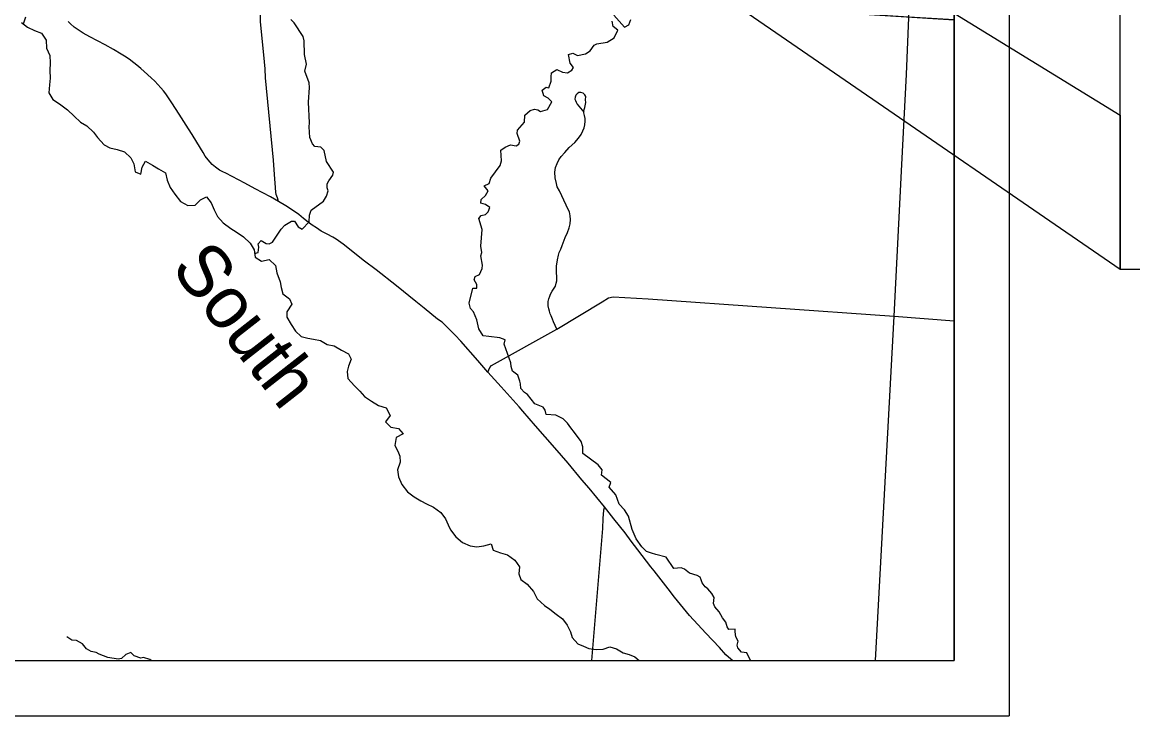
# Model space of a CAD drawing. Extents: x 0 to 91.3, y -0.7 to 22.
# Drawn here: x 7.212 to 9.224, y 14 to 15.256 of the extents above; entities that cross this region are included whole.
import ezdxf

# ---------------------------------------------------------------- set-up
doc = ezdxf.new("R2010")
doc.units = 0
for name, color, linetype in [('GM_X_City_Street', 7, 'Continuous'), ('GM_X_Corporation', 7, 'Continuous'), ('GM_X_County_Road', 7, 'Continuous'), ('GM_X_Major_River', 7, 'Continuous'), ('GM_X_Major_River_Text', 7, 'Continuous'), ('GM_X_Minor_River', 7, 'Continuous'), ('GM_X_Township_Road', 7, 'Continuous'), ('SH_Data', 7, 'Continuous'), ('SH_Text', 7, 'Continuous')]:
    doc.layers.add(name, color=color, linetype=linetype)

msp = doc.modelspace()

# ---------------------------------------------------------------- linework, layer by layer
at = {"layer": 'GM_X_City_Street'}
for points in [[(8.1801, 14.6999), (8.1746, 14.7132), (8.1727, 14.7177), (8.17, 14.7238), (8.1685, 14.7279), (8.1669, 14.7325), (8.1657, 14.7367), (8.1649, 14.742), (8.1645, 14.7461), (8.1649, 14.7499), (8.166, 14.7549), (8.1674, 14.7598), (8.1689, 14.7633), (8.1719, 14.7686), (8.1746, 14.7724), (8.1779, 14.7778), (8.179, 14.7831), (8.1801, 14.7873), (8.1801, 14.7922), (8.1801, 14.796), (8.18, 14.8013), (8.18, 14.8089), (8.1799, 14.8138), (8.1813, 14.8256), (8.1836, 14.8336), (8.1847, 14.8389), (8.1873, 14.8446), (8.1903, 14.8515), (8.1955, 14.8656), (8.1996, 14.8751), (8.2029, 14.8831), (8.2044, 14.8907), (8.2051, 14.8987), (8.2047, 14.9048), (8.2031, 14.9123), (8.2008, 14.9165), (8.1892, 14.9411), (8.1849, 14.9502), (8.181, 14.9577), (8.1795, 14.9638), (8.1771, 14.9736), (8.1767, 14.9839), (8.1777, 14.9923), (8.1811, 14.9995), (8.1837, 15.0067), (8.1882, 15.0125), (8.1946, 15.0197), (8.2025, 15.0285), (8.2131, 15.0377), (8.2199, 15.0454), (8.2244, 15.0522), (8.2274, 15.0591), (8.23, 15.0644), (8.2311, 15.0697), (8.2318, 15.0766), (8.2314, 15.0811), (8.2306, 15.0868), (8.2294, 15.0914), (8.229, 15.0955), (8.2308, 15.1009), (8.2326, 15.11), (8.2322, 15.1153), (8.2326, 15.121), (8.231, 15.124), (8.2283, 15.127), (8.2238, 15.1285), (8.2203, 15.1281), (8.2173, 15.1262), (8.2147, 15.1235), (8.2136, 15.1201), (8.2132, 15.1163), (8.214, 15.114), (8.2152, 15.1106), (8.2171, 15.1072), (8.2202, 15.1034), (8.229, 15.0925)], [(8.2668, 14.378), (8.2647, 14.3725), (8.2638, 14.3573), (8.2633, 14.3391), (8.2434, 14.1)]]:
    msp.add_lwpolyline(points, dxfattribs=at)
at = {"layer": 'GM_X_Corporation'}
msp.add_lwpolyline([(4.8242, 18.6326), (4.7833, 18.1361), (4.7799, 18.0944), (4.7688, 17.9561), (4.7562, 17.8002), (4.7391, 17.5254), (4.7381, 17.5094), (4.7369, 17.4842), (4.7039, 16.921), (4.6966, 16.7952), (4.624, 15.5538), (4.6241, 15.5494), (4.6027, 15.2253), (4.5901, 15.0403), (4.5616, 14.5843), (4.5361, 14.2234), (4.5273, 14.1), (8.9, 14.1), (8.9, 20.9)], dxfattribs=at)
for points in [[(4.5273, 14.1), (8.9, 14.1), (8.9, 15.2596), (8.8181, 15.2648), (7.6407, 15.3389), (7.1732, 15.3725), (6.438, 15.425), (5.7371, 15.476), (5.2553, 15.5081), (4.6241, 15.5494), (4.6027, 15.2253), (4.5901, 15.0403), (4.5616, 14.5843), (4.5361, 14.2234)], [(4.5286, 14.1), (8.9, 14.1), (8.9, 15.2593), (7.6407, 15.3389), (7.1732, 15.3725), (5.7332, 15.4763), (5.3098, 15.5058), (4.9415, 15.5315), (4.9055, 15.5345), (4.624, 15.5538)]]:
    msp.add_lwpolyline(points, close=True, dxfattribs=at)
at = {"layer": 'GM_X_County_Road'}
msp.add_lwpolyline([(8.4988, 14.1), (8.4959, 14.1024), (8.4868, 14.1105), (8.4748, 14.1237), (8.4501, 14.1497), (8.4359, 14.1653), (8.4209, 14.1816), (8.3934, 14.215), (8.3818, 14.2298), (8.357, 14.2621), (8.3507, 14.2697), (8.3273, 14.3005), (8.3152, 14.3159), (8.3039, 14.3309), (8.2837, 14.3564), (8.2668, 14.378), (8.253, 14.3954), (8.2391, 14.4119), (8.2259, 14.4271), (8.2006, 14.4576), (8.1769, 14.4853), (8.1419, 14.525), (8.1188, 14.5515), (8.1121, 14.5591), (8.0794, 14.5955), (8.0555, 14.6222), (8.0371, 14.6432), (8.0064, 14.678), (7.9963, 14.6889), (7.9873, 14.6981), (7.9802, 14.705), (7.9724, 14.7124), (7.9644, 14.7181), (7.9399, 14.7378), (7.9247, 14.7501), (7.8901, 14.7782), (7.8529, 14.8073), (7.8321, 14.8229), (7.7929, 14.8539), (7.7808, 14.8626), (7.7746, 14.8666), (7.7641, 14.8718), (7.7532, 14.8776), (7.7446, 14.8831), (7.7369, 14.8881), (7.7296, 14.8936), (7.7211, 14.9005), (7.7126, 14.9075), (7.7035, 14.9142), (7.6893, 14.9231), (7.6762, 14.931), (7.6617, 14.9393), (7.6339, 14.954), (7.6152, 14.9639), (7.5804, 14.9824), (7.5754, 14.985), (7.5693, 14.988), (7.5645, 14.9915), (7.5618, 14.9934), (7.5559, 14.998), (7.5521, 15.0021), (7.5486, 15.0067), (7.5433, 15.0132), (7.5395, 15.0196), (7.5345, 15.0273), (7.5194, 15.0521), (7.5128, 15.0624), (7.4961, 15.0894), (7.4828, 15.1099), (7.4756, 15.1204), (7.4718, 15.126), (7.4677, 15.1311), (7.4628, 15.1369), (7.452, 15.1488), (7.4455, 15.1549), (7.4326, 15.1665), (7.4265, 15.1719), (7.4194, 15.1781), (7.4141, 15.182), (7.4052, 15.1887), (7.3967, 15.1943), (7.3909, 15.1976), (7.377, 15.2063), (7.3618, 15.2147), (7.3478, 15.2217), (7.3344, 15.2289), (7.322, 15.236), (7.3058, 15.2469), (7.2993, 15.2524), (7.2948, 15.2566)], dxfattribs=at)
at = {"layer": 'GM_X_Major_River'}
for points in [[(7.2106, 15.2553), (7.2212, 15.2469), (7.2337, 15.2408), (7.2465, 15.2358), (7.2548, 15.2233), (7.2559, 15.2085), (7.2616, 15.1952), (7.2623, 15.1823), (7.2614, 15.1679), (7.2622, 15.1543), (7.261, 15.1421), (7.2598, 15.1277), (7.2669, 15.1159), (7.2794, 15.1079), (7.2934, 15.0969), (7.3059, 15.0855), (7.3172, 15.0744), (7.3285, 15.0679), (7.3406, 15.0565), (7.3482, 15.047), (7.3603, 15.0337), (7.3705, 15.0284), (7.3837, 15.0253), (7.397, 15.0207), (7.4083, 15.01), (7.414, 14.999), (7.4162, 14.985), (7.4268, 14.9807), (7.4291, 14.9929), (7.4348, 15.0042), (7.4477, 14.9966), (7.4587, 14.9901), (7.4715, 14.9832), (7.4741, 14.9699), (7.4798, 14.9563), (7.4881, 14.9441), (7.4982, 14.9308), (7.5115, 14.9239), (7.5248, 14.9246), (7.5347, 14.9341), (7.5453, 14.9393), (7.5543, 14.9283), (7.5592, 14.9162), (7.5656, 14.9036), (7.5758, 14.8922), (7.5894, 14.8819), (7.5993, 14.8758), (7.6125, 14.867), (7.6246, 14.8556), (7.6317, 14.8435), (7.634, 14.8302), (7.6453, 14.8229), (7.659, 14.8263), (7.6703, 14.8149), (7.6733, 14.802), (7.6793, 14.7857), (7.6811, 14.7754), (7.6837, 14.7637), (7.6962, 14.7549), (7.7004, 14.745), (7.6912, 14.7314), (7.6912, 14.7219), (7.6987, 14.7086), (7.7066, 14.6961), (7.7172, 14.6869), (7.7293, 14.6835), (7.7395, 14.6815), (7.752, 14.6792), (7.7645, 14.672), (7.777, 14.6697), (7.7899, 14.662), (7.8028, 14.6551), (7.8076, 14.6453), (7.8027, 14.6332), (7.8007, 14.6233), (7.8018, 14.6104), (7.8139, 14.5975), (7.8233, 14.5876), (7.832, 14.5777), (7.8445, 14.5697), (7.8574, 14.5617)], [(7.8574, 14.5617), (7.871, 14.5575), (7.8785, 14.5438), (7.8698, 14.5321), (7.8796, 14.5225), (7.8936, 14.5198), (7.9019, 14.5103), (7.889, 14.5035), (7.8867, 14.4892), (7.8923, 14.4793), (7.8957, 14.4698), (7.8964, 14.4592), (7.8914, 14.4455), (7.8933, 14.4323), (7.8997, 14.4186), (7.9099, 14.4053), (7.9216, 14.3961), (7.9337, 14.3889), (7.9443, 14.3839), (7.9571, 14.3774), (7.97, 14.3679), (7.9787, 14.3565), (7.9835, 14.3459), (7.9877, 14.3364), (7.9975, 14.3242), (8.0096, 14.3139), (8.0232, 14.3078), (8.0353, 14.3058), (8.0482, 14.3077), (8.0611, 14.3114), (8.0649, 14.3), (8.0781, 14.2951), (8.091, 14.2912), (8.1042, 14.2817), (8.1125, 14.2695), (8.1117, 14.257), (8.1151, 14.2464), (8.1268, 14.2384), (8.1378, 14.2247), (8.1449, 14.2118), (8.1578, 14.1996), (8.1676, 14.1931), (8.1789, 14.184), (8.1906, 14.1756), (8.1989, 14.1638), (8.205, 14.152), (8.208, 14.1418), (8.2185, 14.1304), (8.2284, 14.1258), (8.2386, 14.122), (8.2515, 14.12), (8.2644, 14.1207), (8.2765, 14.1245), (8.2883, 14.1214), (8.3004, 14.1141), (8.3117, 14.1107), (8.3216, 14.1068), (8.3294, 14.1)]]:
    msp.add_lwpolyline(points, dxfattribs=at)
at = {"layer": 'GM_X_Minor_River'}
for points in [[(7.2141, 15.2526), (7.2183, 15.2654)], [(7.6328, 14.8369), (7.639, 14.8387), (7.6402, 14.8481), (7.6391, 14.8542), (7.6444, 14.8606), (7.6535, 14.8549), (7.6592, 14.8545), (7.6649, 14.8575), (7.6806, 14.8809), (7.6874, 14.8884), (7.6996, 14.8952), (7.7053, 14.8952), (7.7117, 14.8853), (7.7188, 14.881), (7.7314, 14.8939), (7.7319, 14.906), (7.735, 14.9151), (7.7578, 14.9316), (7.7632, 14.9407), (7.7662, 14.9505), (7.7644, 14.9555), (7.7644, 14.963), (7.7675, 14.9683), (7.7747, 14.9789), (7.7755, 14.9842), (7.7631, 15.0036), (7.7587, 15.0234), (7.753, 15.0291), (7.7417, 15.0303), (7.7375, 15.0356), (7.7327, 15.0467), (7.7316, 15.066), (7.7321, 15.0732), (7.7304, 15.1111), (7.7324, 15.1373), (7.7313, 15.146), (7.7239, 15.1669), (7.727, 15.1798), (7.7229, 15.1969), (7.7223, 15.2219), (7.7208, 15.2295), (7.7043, 15.2542), (7.6982, 15.2607)], [(8.0487, 14.9595), (8.0575, 14.9636), (8.0609, 14.9734), (8.0774, 14.9964), (8.0801, 15.0044), (8.079, 15.0237), (8.087, 15.0294), (8.0965, 15.0335), (8.1064, 15.0319), (8.1113, 15.0349), (8.1136, 15.0402), (8.1084, 15.0543), (8.1092, 15.0603), (8.1218, 15.0747), (8.1222, 15.0872), (8.1318, 15.0958), (8.1401, 15.0981), (8.1458, 15.0969), (8.1507, 15.0938), (8.1632, 15.0975), (8.1713, 15.1112), (8.1649, 15.118), (8.1566, 15.1226), (8.1536, 15.1325), (8.1608, 15.1381), (8.1657, 15.137), (8.17, 15.1487), (8.17, 15.157), (8.1708, 15.1642), (8.1803, 15.1699), (8.1909, 15.1653), (8.1996, 15.1641), (8.2076, 15.1686), (8.2103, 15.1735), (8.2043, 15.1815), (8.2013, 15.197), (8.2093, 15.1993), (8.218, 15.1954), (8.2324, 15.1984), (8.2408, 15.2036), (8.2477, 15.2142), (8.253, 15.2164), (8.2716, 15.2194), (8.2845, 15.2276), (8.2911, 15.2412), (8.2824, 15.2481), (8.2809, 15.2572)], [(8.2836, 15.2682), (8.3028, 15.2465), (8.3108, 15.2506), (8.3147, 15.2604)], [(8.5313, 14.1), (8.5247, 14.1138), (8.5152, 14.1154), (8.5084, 14.123), (8.507, 14.1279), (8.5089, 14.1351), (8.5044, 14.1427), (8.5033, 14.1518), (8.5037, 14.1568), (8.492, 14.1561), (8.4889, 14.161), (8.4867, 14.1694), (8.4803, 14.1774), (8.4743, 14.1884), (8.4668, 14.1972), (8.4642, 14.2033), (8.4654, 14.2139), (8.4609, 14.2215), (8.4541, 14.2299), (8.4492, 14.2333), (8.4439, 14.2409), (8.442, 14.2462), (8.4398, 14.2512), (8.4349, 14.2542), (8.4205, 14.2581), (8.4114, 14.2657), (8.4058, 14.2681), (8.3925, 14.2666), (8.3786, 14.2872), (8.3597, 14.2922), (8.3517, 14.2945), (8.3426, 14.2976), (8.3343, 14.3056), (8.3242, 14.3201), (8.3171, 14.3372), (8.31, 14.3611), (8.3032, 14.3729), (8.2934, 14.3832), (8.2871, 14.3999), (8.275, 14.414), (8.2781, 14.4224), (8.2615, 14.4354), (8.2623, 14.4452), (8.2555, 14.4544), (8.2276, 14.475), (8.2273, 14.4871), (8.2243, 14.4966), (8.2123, 14.5126), (8.2059, 14.5214), (8.1999, 14.5298), (8.1919, 14.5374), (8.1783, 14.5443), (8.1613, 14.5455), (8.1594, 14.5531), (8.1553, 14.5588), (8.1402, 14.5646), (8.1274, 14.5814), (8.1217, 14.5852), (8.1153, 14.5924), (8.1146, 14.6008), (8.1131, 14.6057), (8.1094, 14.6167), (8.1003, 14.6236), (8.0973, 14.632), (8.097, 14.6388), (8.085, 14.673), (8.087, 14.6806), (8.0771, 14.6844), (8.0571, 14.6864), (8.0468, 14.6876), (8.0393, 14.7006), (8.0352, 14.7165), (8.0293, 14.731), (8.024, 14.7371), (8.0214, 14.7469), (8.028, 14.7742), (8.0352, 14.7741), (8.0352, 14.7806), (8.0303, 14.7893), (8.0323, 14.795), (8.0403, 14.7991), (8.0452, 14.8097), (8.0457, 14.8158), (8.0427, 14.8325), (8.0443, 14.8389), (8.0424, 14.8499), (8.0453, 14.8806), (8.0393, 14.9), (8.0435, 14.9057), (8.0511, 14.9075), (8.0561, 14.9124), (8.0587, 14.92), (8.0508, 14.9253), (8.0425, 14.928), (8.0433, 14.9349), (8.0509, 14.9416), (8.0559, 14.9503), (8.0487, 14.9595)], [(7.445, 14.1), (7.4427, 14.1017), (7.4317, 14.1052), (7.4267, 14.1044), (7.4146, 14.1083), (7.4086, 14.1148), (7.3995, 14.1107), (7.3915, 14.1039), (7.3858, 14.1024), (7.3669, 14.1055), (7.351, 14.1117), (7.3457, 14.1144), (7.3366, 14.1163), (7.3283, 14.1213), (7.3211, 14.1305), (7.3098, 14.1362), (7.3014, 14.137), (7.2924, 14.1431)]]:
    msp.add_lwpolyline(points, dxfattribs=at)
at = {"layer": 'GM_X_Township_Road'}
msp.add_line((8.7914, 14.7233), (8.9, 14.715), dxfattribs=at)
for points in [[(7.6762, 14.931), (7.6742, 14.9379), (7.6719, 14.9435), (7.6712, 14.9479), (7.6679, 14.9886), (7.667, 15.0056), (7.6526, 15.1549), (7.6518, 15.1712), (7.6497, 15.1966), (7.6435, 15.2562), (7.6434, 15.2572), (7.6439, 15.3006), (7.641, 15.3374)], [(8.7578, 14.1), (8.7914, 14.7233), (8.8057, 14.9979), (8.8139, 15.1608), (8.8183, 15.2643), (8.8189, 15.2791)], [(8.0555, 14.6222), (8.0572, 14.6264), (8.0592, 14.6304), (8.0619, 14.6342), (8.1801, 14.6999), (8.2624, 14.7494), (8.274, 14.7565), (8.2826, 14.7583), (8.3461, 14.755), (8.7914, 14.7233)]]:
    msp.add_lwpolyline(points, dxfattribs=at)
at = {"layer": 'SH_Data'}
for p, q in [((9, 21), (9, 14)), ((8.9, 20.9), (8.9, 14.1)), ((2.1, 14.1), (8.9, 14.1)), ((2, 14), (9, 14))]:
    msp.add_line(p, q, dxfattribs=at)
at = {"layer": 'SH_Text'}
for points in [[(9.2012, 14.8079), (5.3743, 17.4358), (9.2012, 15.0876)], [(9.2012, 15.5404), (11.1395, 15.5404), (11.1395, 14.8079), (9.2012, 14.8079)]]:
    msp.add_lwpolyline(points, close=True, dxfattribs=at)

# ---------------------------------------------------------------- texts
at = {"layer": 'GM_X_Major_River_Text'}
msp.add_text('South', height=0.09469, rotation=308.0008, dxfattribs=at).set_placement((7.4792, 14.8099))

doc.saveas('drawing.dxf')
